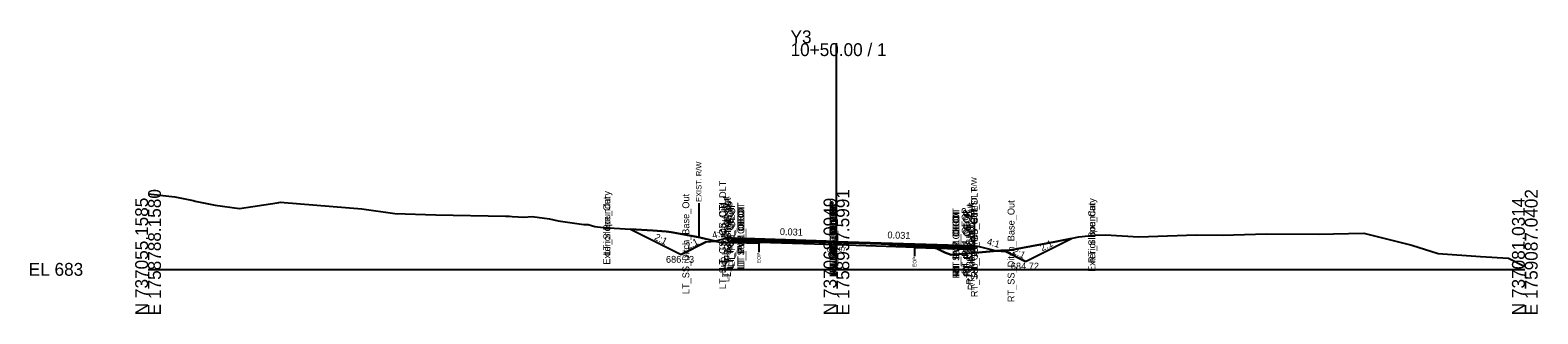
# Model space of a CAD drawing. Extents: x -26 to 1760432, y -10 to 737112.
# Drawn here: x -25.7 to 302.8, y 490.3 to 552.1 of the extents above; entities that cross this region are included whole.
import ezdxf

# ---------------------------------------------------------------- set-up
doc = ezdxf.new("R2010")
doc.units = 0
for name, color, linetype in [('Default', 7, 'Continuous'), ('Exist Cross Section Cell', 7, 'Continuous'), ('Exist XS Center Line Elevation Label', 7, 'Continuous'), ('Exist XS Ground Line', 7, 'Continuous'), ('Old_Level_10', 7, 'Continuous'), ('Prop CMT Pvmt Course 1', 7, 'Continuous'), ('Prop CMT Pvmt Course 2', 7, 'Continuous'), ('Prop CMT Pvmt Course 3', 7, 'Continuous'), ('Prop CMT Pvmt Surface', 7, 'Continuous'), ('Prop CMT Pvmt Surface Shoulder', 7, 'Continuous'), ('Prop CMT Pvmt Wedge Surface 1', 7, 'Continuous'), ('Prop CMT Shld Paved Course 1', 7, 'Continuous'), ('Prop CMT Shld Paved Course 2', 7, 'Continuous'), ('Prop CMT Shld Paved Course 3', 7, 'Continuous'), ('Prop CMT Slope Grass', 7, 'Continuous'), ('Prop CMT Subgrade Earthwork', 7, 'Continuous'), ('Prop XS DDE', 7, 'Continuous'), ('Prop XS Ditch Standard Text', 7, 'Continuous'), ('Prop XS Earthwork Shape', 7, 'Continuous'), ('Prop XS SE Text', 7, 'Continuous'), ('Prop XS Side Slope Text', 7, 'Continuous'), ('Scratch_Level_5', 7, 'Continuous'), ('Scratch_Level_7', 7, 'Continuous')]:
    doc.layers.add(name, color=color, linetype=linetype)

msp = doc.modelspace()

# ---------------------------------------------------------------- linework, layer by layer
at = {"layer": 'Exist Cross Section Cell'}
for p, q in [((150, 500), (150, 549.26)), ((0, 500), (150, 500)), ((150, 500), (300, 500))]:
    msp.add_line(p, q, dxfattribs=at)
at = {"layer": 'Exist XS Ground Line'}
msp.add_lwpolyline([(0, 516.42), (5.18, 515.84), (5.82, 515.77), (9.84, 515.02), (10.25, 514.88), (14.6, 514.01), (19.96, 513.29), (28.11, 514.5), (28.84, 514.61), (29.68, 514.54), (46.59, 513.15), (53.77, 512.15), (62.72, 511.85), (77.92, 511.57), (78.75, 511.56), (79.36, 511.49), (80.62, 511.41), (81.87, 511.36), (83.72, 511.52), (87.44, 511), (89.36, 510.59), (94.93, 509.74), (95.89, 509.74), (97.36, 509.33), (99.2, 509.11), (109.98, 508.45), (112.9, 508.28), (113.49, 508.19), (114.02, 508.09), (120.21, 506.95), (124.81, 505.87), (130.41, 505.81), (133.04, 505.81), (133.38, 505.83), (135.01, 505.9), (136.1, 505.97), (137.81, 505.98), (138.61, 505.98), (140.12, 505.99), (141.12, 505.99), (142.43, 505.99), (143.63, 505.99), (144.74, 505.97), (146.14, 505.95), (147.05, 505.94), (148.65, 505.91), (149.36, 505.89), (150, 505.87), (151.16, 505.85), (151.67, 505.83), (153.66, 505.76), (153.98, 505.75), (156.17, 505.72), (157.6, 505.66), (158.68, 505.61), (161.19, 505.46), (163.22, 505.35), (163.7, 505.32), (165.15, 505.16), (166.1, 505.07), (167.89, 504.85), (170.06, 505.38), (173.6, 503.7), (175.01, 503.19), (180.25, 503.6), (185.79, 504.12), (187.41, 504.11), (197.56, 505.96), (202.8, 507.07), (206.29, 507.45), (208.64, 507.49), (215.86, 507.05), (228.37, 507.53), (234.15, 507.42), (243.68, 507.71), (254.95, 507.68), (264.93, 507.85), (275.41, 505.29), (281.11, 503.44), (290.33, 502.82), (296.41, 502.47), (300, 500.64)], dxfattribs=at)
at = {"layer": 'Old_Level_10'}
for p, q in [((120, 514.39), (120, 506.99)), ((180, 510.98), (180, 503.58)), ((133.08, 505.81), (133.08, 503.76)), ((167.03, 504.94), (167.03, 502.89))]:
    msp.add_line(p, q, dxfattribs=at)
at = {"layer": 'Prop CMT Pvmt Course 1'}
for points in [[(150, 506.1), (129.93, 506.71)], [(129.93, 506.71), (129.93, 506.46)], [(129.93, 506.46), (150, 505.85)], [(150, 505.85), (150, 506.1)], [(150, 506.1), (176.8, 505.27)], [(176.8, 505.02), (150, 505.85)], [(176.8, 505.27), (176.8, 505.02)]]:
    msp.add_lwpolyline(points, dxfattribs=at)
msp.add_lwpolyline([(150, 505.85), (150, 505.97), (150, 505.97), (150, 505.85)], close=True, dxfattribs=at)
at = {"layer": 'Prop CMT Pvmt Course 2'}
for p, q in [((161.19, 505.46), (159.81, 505.55)), ((163.7, 505.32), (161.19, 505.46)), ((165.15, 505.16), (163.7, 505.32)), ((167.03, 504.95), (165.15, 505.16)), ((167.03, 504.95), (167.03, 505.32))]:
    msp.add_line(p, q, dxfattribs=at)
for points in [[(150, 505.85), (129.93, 506.46)], [(129.93, 506.46), (129.93, 506.25)], [(129.93, 506.25), (138.84, 505.98)], [(150, 505.85), (176.8, 505.02)], [(176.8, 504.82), (167.03, 505.12)], [(176.8, 505.02), (176.8, 504.82)]]:
    msp.add_lwpolyline(points, dxfattribs=at)
at = {"layer": 'Prop CMT Pvmt Course 3'}
for p, q in [((135.01, 505.9), (136.1, 505.97)), ((136.1, 505.97), (138.84, 505.98)), ((133.25, 505.82), (135.01, 505.9)), ((167.03, 505.12), (167.03, 504.94))]:
    msp.add_line(p, q, dxfattribs=at)
for points in [[(138.84, 505.98), (129.93, 506.25)], [(129.93, 506.25), (129.93, 505.92)], [(129.93, 505.92), (133.25, 505.82)], [(167.03, 505.12), (176.8, 504.82)], [(176.8, 504.82), (176.8, 504.48)]]:
    msp.add_lwpolyline(points, dxfattribs=at)
at = {"layer": 'Prop CMT Pvmt Surface'}
for points in [[(150, 506.1), (129.93, 506.71)], [(150, 506.1), (176.8, 505.27)]]:
    msp.add_lwpolyline(points, dxfattribs=at)
at = {"layer": 'Prop CMT Pvmt Surface Shoulder'}
for points in [[(129.93, 506.71), (127.93, 506.77)], [(176.8, 505.27), (178.8, 505.21)]]:
    msp.add_lwpolyline(points, dxfattribs=at)
at = {"layer": 'Prop CMT Pvmt Wedge Surface 1'}
for p, q in [((133.08, 505.82), (133.08, 506.49)), ((150, 505.97), (133.08, 506.49)), ((133.08, 506.49), (133.08, 506.37)), ((147.09, 505.94), (133.08, 506.37)), ((133.08, 506.37), (133.08, 506.16)), ((133.08, 506.37), (147.09, 505.94)), ((133.08, 506.16), (138.84, 505.98)), ((138.84, 505.98), (133.08, 506.16)), ((133.08, 506.16), (133.08, 505.82)), ((135.01, 505.9), (136.1, 505.97)), ((136.1, 505.97), (136.81, 505.97)), ((150, 505.88), (150, 505.97)), ((150, 505.97), (150, 505.97)), ((167.03, 505.45), (150, 505.97)), ((150, 505.97), (150, 505.88)), ((133.08, 505.82), (133.25, 505.82)), ((167.03, 505.32), (159.81, 505.55)), ((159.81, 505.55), (161.19, 505.46)), ((159.81, 505.55), (167.03, 505.32)), ((163.7, 505.32), (165.15, 505.16)), ((167.03, 505.32), (167.03, 505.45)), ((167.03, 505.32), (167.03, 505.45)), ((167.03, 505.12), (167.03, 505.32)), ((167.03, 504.95), (167.03, 505.12))]:
    msp.add_line(p, q, dxfattribs=at)
for points in [[(150, 505.97), (133.08, 506.49)], [(136.81, 505.97), (138.61, 505.98), (138.84, 505.98)], [(138.84, 505.98), (139.56, 505.98), (141.12, 505.99), (142.3, 505.99), (143.63, 505.99), (145.05, 505.97), (146.14, 505.95), (147.09, 505.94)], [(138.84, 505.98), (138.84, 505.98)], [(150, 505.97), (167.03, 505.45)], [(133.25, 505.82), (133.38, 505.83), (135.01, 505.9)], [(147.09, 505.94), (147.8, 505.92), (148.65, 505.91), (150, 505.88)], [(150, 505.88), (150, 505.88)], [(150, 505.88), (150.54, 505.87), (151.16, 505.85), (153.29, 505.77), (153.66, 505.76), (156.17, 505.72), (157.6, 505.66), (158.68, 505.61), (159.81, 505.55)], [(161.19, 505.46), (161.53, 505.44), (163.7, 505.32)], [(165.15, 505.16), (166.1, 505.07), (167.03, 504.95)]]:
    msp.add_lwpolyline(points, dxfattribs=at)
at = {"layer": 'Prop CMT Shld Paved Course 1'}
for points in [[(129.93, 506.71), (127.93, 506.77), (127.69, 506.53)], [(127.69, 506.53), (129.93, 506.46)], [(129.93, 506.46), (129.93, 506.71)], [(176.8, 505.27), (178.8, 505.21), (179.06, 504.96)], [(176.8, 505.02), (176.8, 505.27)], [(179.06, 504.96), (176.8, 505.02)]]:
    msp.add_lwpolyline(points, dxfattribs=at)
at = {"layer": 'Prop CMT Shld Paved Course 2'}
for points in [[(129.93, 506.46), (127.69, 506.53), (127.49, 506.33)], [(127.49, 506.33), (129.93, 506.25)], [(129.93, 506.25), (129.93, 506.46)], [(176.8, 505.02), (179.06, 504.96), (179.28, 504.74)], [(176.8, 504.82), (176.8, 505.02)], [(179.28, 504.74), (176.8, 504.82)]]:
    msp.add_lwpolyline(points, dxfattribs=at)
at = {"layer": 'Prop CMT Shld Paved Course 3'}
for points in [[(129.93, 506.25), (127.49, 506.33), (126.99, 506.35), (126.66, 506.02)], [(126.66, 506.02), (129.93, 505.92)], [(129.93, 505.92), (129.93, 506.25)], [(176.8, 504.82), (179.28, 504.74), (179.78, 504.73), (180.12, 504.38)], [(176.8, 504.48), (176.8, 504.82)], [(180.12, 504.38), (176.8, 504.48)]]:
    msp.add_lwpolyline(points, dxfattribs=at)
at = {"layer": 'Prop CMT Slope Grass'}
for points in [[(127.93, 506.77), (125.93, 506.72), (123.64, 506.14)], [(178.8, 505.21), (180.8, 505.05), (184.88, 504.03)]]:
    msp.add_lwpolyline(points, dxfattribs=at)
at = {"layer": 'Prop CMT Subgrade Earthwork'}
for p, q in [((133.08, 505.82), (133.08, 505.81)), ((167.03, 504.78), (167.03, 504.94))]:
    msp.add_line(p, q, dxfattribs=at)
for points in [[(126.66, 506.02), (125.97, 506.72)], [(129.93, 505.92), (126.66, 506.02)], [(133.08, 505.82), (129.93, 505.92)], [(167.03, 504.78), (176.8, 504.48)], [(176.8, 504.48), (180.12, 504.38)], [(180.12, 504.38), (180.79, 505.05)]]:
    msp.add_lwpolyline(points, dxfattribs=at)
at = {"layer": 'Prop XS DDE'}
for p, q in [((105.09, 508.75), (116.13, 503.23)), ((121.64, 505.98), (116.13, 503.23)), ((121.64, 505.98), (123.64, 506.14)), ((191.19, 501.72), (201.23, 506.74)), ((186.88, 503.87), (184.88, 504.03)), ((191.19, 501.72), (186.88, 503.87))]:
    msp.add_line(p, q, dxfattribs=at)
at = {"layer": 'Prop XS Earthwork Shape'}
for points in [[(129.93, 505.92), (126.66, 506.02), (125.97, 506.72), (125.93, 506.72), (123.64, 506.14), (124.81, 505.87), (130.41, 505.81), (133.04, 505.81), (133.25, 505.82)], [(150, 505.31), (133.25, 505.82), (133.38, 505.83), (135.01, 505.9), (136.1, 505.97), (136.81, 505.97), (138.61, 505.98), (139.56, 505.98), (141.12, 505.99), (142.3, 505.99), (143.63, 505.99), (145.05, 505.97), (146.14, 505.95), (147.8, 505.92), (148.65, 505.91), (150, 505.88), (150.54, 505.87), (151.16, 505.85), (153.29, 505.77), (153.66, 505.76), (156.17, 505.72), (157.6, 505.66), (158.68, 505.61), (161.19, 505.46), (161.53, 505.44), (163.7, 505.32), (165.15, 505.16), (166.1, 505.07), (167.89, 504.85), (170.06, 505.38), (171.61, 504.64)], [(180.12, 504.38), (180.79, 505.05), (180.8, 505.05), (184.88, 504.03), (180.25, 503.6), (175.01, 503.19), (173.6, 503.7), (171.61, 504.64), (176.8, 504.48)]]:
    msp.add_lwpolyline(points, close=True, dxfattribs=at)
at = {"layer": 'Scratch_Level_5'}
for p, q in [((105.09, 508.75), (116.13, 503.23)), ((116.13, 503.23), (121.64, 505.98)), ((123.64, 506.14), (120.21, 506.95)), ((121.64, 505.98), (123.64, 506.14)), ((191.19, 501.72), (201.23, 506.74)), ((201.23, 506.74), (197.56, 505.96)), ((184.88, 504.03), (186.88, 503.87)), ((186.88, 503.87), (191.19, 501.72))]:
    msp.add_line(p, q, dxfattribs=at)
for points in [[(120.21, 506.95), (120, 506.99), (114.02, 508.09), (113.49, 508.19), (112.9, 508.28), (109.98, 508.45), (105.09, 508.75)], [(197.56, 505.96), (187.41, 504.11), (185.79, 504.12), (184.88, 504.03)]]:
    msp.add_lwpolyline(points, dxfattribs=at)

# ---------------------------------------------------------------- texts
at = {"layer": 'Default'}
msp.add_text('-', height=0.0001, dxfattribs=at).set_placement((0, 500))
at = {"layer": 'Exist Cross Section Cell'}
for s, p in [('Y3', (140, 549.26)), ('10+50.00 / 1', (140, 546.46)), ('EL 683', (-26, 498.6))]:
    msp.add_text(s, height=2.8, dxfattribs=at).set_placement(p)
for s, p in [('E 1758788.1580', (2.8, 490)), ('E 1758937.5991', (152.8, 490)), ('E 1759087.0402', (302.8, 490)), ('N 737055.1585', (0, 490)), ('N 737068.0949', (150, 490)), ('N 737081.0314', (300, 490))]:
    msp.add_text(s, height=2.8, rotation=90, dxfattribs=at).set_placement(p)
at = {"layer": 'Exist XS Center Line Elevation Label'}
msp.add_text('688.87', height=1, dxfattribs=at).set_placement((147.85, 503.87))
at = {"layer": 'Old_Level_10'}
for s, height, p in [('EXIST. R/W', 1.181, (120.59, 514.69)), ('EXIST. R/W', 1.181, (180.59, 511.28)), ('EOP', 0.787, (133.48, 501.36)), ('EOP', 0.787, (167.43, 500.5))]:
    msp.add_text(s, height=height, rotation=90, dxfattribs=at).set_placement(p)
at = {"layer": 'Prop XS Ditch Standard Text'}
for s, p in [('686.23', (112.85, 501.43)), ('684.72', (188, 499.95))]:
    msp.add_text(s, height=1.5, dxfattribs=at).set_placement(p)
at = {"layer": 'Prop XS SE Text'}
for p in [(137.65, 507.48), (161.09, 506.76)]:
    msp.add_text('0.031', height=1.5, rotation=358.2423, dxfattribs=at).set_placement(p)
at = {"layer": 'Prop XS Side Slope Text'}
for s, rotation, p in [('2:1', 333.4349, (110.18, 506.54)), ('2:1', 26.5651, (117.6, 504.28)), ('4:1', 14.0362, (123.1, 506.67)), ('4:1', 345.9638, (182.69, 505.36)), ('2:1', 26.5651, (194.83, 503.92)), ('2:1', 333.4349, (188.24, 503.53))]:
    msp.add_text(s, height=1.5, rotation=rotation, dxfattribs=at).set_placement(p)
at = {"layer": 'Scratch_Level_7'}
for s, p in [('LT_Sub_Trench_Out_DLT', (125.97, 495.69)), ('Exterior Boundary', (100.71, 501.01)), ('LT_Slope_Cut', (100.71, 503.03)), ('LT_SS_Ditch_Base_Out', (117.93, 494.6)), ('LT_Sub_Trench_Out', (126.66, 497.19)), ('RT_Sub_Trench_Out_DLT', (180.79, 493.94)), ('LT_GS_OS_CTL', (125.93, 499.91)), ('LT_PS3_Shelf_Out', (126.99, 498.33)), ('LT_PS3_OEOP', (127.49, 500.01)), ('LT_PS2_OEOP', (127.69, 500.21)), ('LT_PS1_OEOP', (127.93, 500.63)), ('LT_Sub_OEOT', (129.93, 499.57)), ('LT_PV1_OEOT', (129.93, 500.51)), ('LT_PV2_OEOT', (129.93, 500.08)), ('LT_PV3_OEOT', (129.93, 499.87)), ('RT_Sub_OEEOP', (150, 498.34)), ('LT_Sub_OEEOP', (150, 498.43)), ('RT_PV1_OEEOP', (150, 499.15)), ('LT_PV1_OEEOP', (150, 499.24)), ('RT_PV2_OEEOP', (150, 498.85)), ('RT_PV1_IEEOP', (150, 499.72)), ('RT_PV3_OEEOP', (150, 498.64)), ('LT_PV2_OEEOP', (150, 498.94)), ('LT_PV1_IEEOP', (150, 499.81)), ('RT_PV2_IEEOP', (150, 499.42)), ('LT_PV3_OEEOP', (150, 498.73)), ('LT_PV2_IEEOP', (150, 499.51)), ('RT_PV1_OEOT', (176.8, 498.98)), ('RT_PV2_OEOT', (176.8, 498.55)), ('RT_PV3_OEOT', (176.8, 498.35)), ('RT_PS1_OEOP', (178.8, 498.98)), ('RT_PS2_OEOP', (179.06, 498.55)), ('RT_PS3_OEOP', (179.28, 498.33)), ('RT_PS3_Shelf_Out', (179.78, 496.62)), ('RT_Sub_Trench_Out', (180.12, 495.46)), ('RT_GS_OS_CTL', (180.8, 498.16)), ('RT_SS_Ditch_Base_Out', (188.8, 492.85)), ('Exterior Boundary', (206.4, 499.44)), ('RT_Slope_Cut', (206.4, 501.37)), ('PV1_PGL', (150, 502.3)), ('PV2_PGL', (150, 501.87)), ('RT_Sub_OEOT', (176.8, 498.05))]:
    msp.add_text(s, height=1.5, rotation=90, dxfattribs=at).set_placement(p)

doc.saveas('drawing.dxf')
